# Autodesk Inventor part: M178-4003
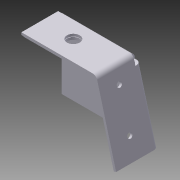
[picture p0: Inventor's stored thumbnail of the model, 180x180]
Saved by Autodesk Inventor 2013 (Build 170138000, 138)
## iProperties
Created: 2008-02
Part Number: M178-4003
Material: Aluminium - 6061
Document SubType Name: Sheet Metal
Designer: Autodesk, Inc.
Mass: 22.5137 g
Surface Area: 116.065 cm^2
Volume: 8.30765 cm^3
Density: 2.71 g/cm^3
Flat Pattern Width: 8.18641 cm
Flat Pattern Length: 9.33965 cm
Flat Pattern Area: 76.4582 cm^2
Sheet Metal Rule: Default
Sheet Metal Width: 3.223 in
Sheet Metal Length: 3.677 in
Sheet Metal Area: 11.851 in^2
Author: Autodesk, Inc.
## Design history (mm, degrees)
node "Face1"
node "Flange1"
cut "Cut1" dims "d16" = 1.524 (= Thickness), "d17" = 0
node "Flange2"
node "Flange3"
sketch "Sketch6"
  geometry: L1 (0, 0)-(23.876, 0) reference; L2 (23.876, 0)-(23.876, 45.72) reference; 3 further points
  constraints: 2 vertical alignment, 1 midpoint
  dimensions: "d45" = 25.4 distance of point (11.938, 12.7) point (11.938, 38.1); "d46" = 12.7 distance from line of L1 point (11.938, 12.7); "d47" = 11.938 distance from line of point (11.938, 0) L2 (derived)
hole "Hole1" sketch "Sketch6" diameter "d48" = 3.175; stored, may be unused: countersink angle "d52" = 82 deg, drill point angle "d54" = 118 deg; dims "d49" = 12.7, "d50" = 9.525, "d51" = 6.35, "d53" = 1.524 (= Thickness)
sketch "Sketch7"
  geometry: L1 (0, 0)-(0, 22.352) reference; 2 further points
  constraints: 1 horizontal alignment, 1 midpoint
  dimensions: "d55" = 20 distance from line of point (20, 11.176) L1
hole "Hole2" sketch "Sketch7" diameter "d56" = 8; stored, may be unused: countersink angle "d60" = 82 deg, drill point angle "d62" = 118 deg; dims "d57" = 12.7, "d58" = 9.525, "d59" = 6.35, "d61" = 1.524 (= Thickness)
body "Solid1"
sketch "Sketch1"
  geometry: L1 (0, 0)-(59.639, 0); L2 (59.639, 0)-(47.625, 44.628); L3 (47.625, 44.628)-(0, 44.628); L4 (0, 44.628)-(0, 0)
  constraints: 8 end point, 1 horizontal, 1 parallel, 1 vertical
  dimensions: "d0" = 44.6278 distance of L3.end L1.start; "d1" = 59.6392 distance of L1.start L1.end; "d2" = 47.625 distance of L2.end L3.end; "d34" = 105.067 deg angle of L2 L3 (derived)
face "Plate1" dims "Thickness" = 1.524
sketch "Sketch2"
  geometry: L1 through (-22.225, 0) direction (-1, 8.16e-34); L2 (-44.45, 0)-(-44.45, 25.4); L3 (-44.45, 25.4)-(0, 25.4); L4 through (0, 12.7) direction (0, -1)
  constraints: 6 end point, 1 horizontal, 1 perpendicular, 1 vertical
face "Plate2" dims "d4" = 1.524 (= BendReliefWidth), "d5" = 0.762 (= BendReliefDepth), "d6" = 3.048 (= MinimumRemnant), "d7" = 1.524 (= BendRadius), "d8" = 25.4, "d9" = 90 deg, "d10" = 1.524 (= BendRadius), "d11" = 6.096 (= CornerReliefSize), "d12" = 1.524 (= Thickness), "d13" = 1.524 (= JacobiRadiusSize), "d18" = 44.45, "d19" = 0, "SeamGap" = 0.00508, "Thickness" = 1.524
bend "Bend1" dims "d4" = 1.524 (= BendReliefWidth), "d5" = 0.762 (= BendReliefDepth), "d6" = 3.048 (= MinimumRemnant), "d7" = 1.524 (= BendRadius), "d8" = 25.4, "d9" = 90 deg, "d10" = 1.524 (= BendRadius), "SeamGap" = 0.00508, "Thickness" = 1.524
feature "Corner1" dims "d8" = 25.4, "d9" = 90 deg, "d11" = 6.096 (= CornerReliefSize), "d12" = 1.524 (= Thickness), "d13" = 1.524 (= JacobiRadiusSize)
sketch "Sketch3"
  geometry: L1 (0, -22.352)-(0, 0) reference; L2 (0, 0)-(44.45, 0) reference; L3 (44.45, -22.352)-(44.45, 0) reference; L4 (39.472, 0)-(44.45, -18.567)
  constraints: 2 end point, 2 point on line
  dimensions: "d20" = 4.9784 distance from line of L4.start L3; "d21" = 18.5674 distance from line of L4.end L2
sketch "Sketch4"
  geometry: L1 (-42.271, 0)-(3.449, 0); L2 (3.449, 0)-(3.449, 26.924); L3 (3.449, 26.924)-(-42.271, 26.924); L4 (-42.271, 26.924)-(-42.271, 0)
  constraints: 8 end point
face "Plate3" dims "d22" = 1.524 (= BendReliefWidth), "d23" = 0.762 (= BendReliefDepth), "d24" = 3.048 (= MinimumRemnant), "d25" = 1.524 (= BendRadius), "d26" = 25.4, "d27" = 90 deg, "d28" = 1.524 (= BendRadius), "d29" = 6.096 (= CornerReliefSize), "d30" = 1.524 (= Thickness), "d31" = 1.524 (= JacobiRadiusSize), "d32" = 45.72, "d33" = 0, "SeamGap" = 0.00508, "Thickness" = 1.524
bend "Bend2" dims "d22" = 1.524 (= BendReliefWidth), "d23" = 0.762 (= BendReliefDepth), "d24" = 3.048 (= MinimumRemnant), "d25" = 1.524 (= BendRadius), "d26" = 25.4, "d27" = 90 deg, "d28" = 1.524 (= BendRadius), "SeamGap" = 0.00508, "Thickness" = 1.524
feature "Corner2" dims "d26" = 25.4, "d27" = 90 deg, "d29" = 6.096 (= CornerReliefSize), "d30" = 1.524 (= Thickness), "d31" = 1.524 (= JacobiRadiusSize)
sketch "Sketch5"
  geometry: L1 through (0, 11.557) direction (-2.13e-32, -1); L2 through (22.403, 0) direction (1, 8.58e-34); L3 (44.806, 0)-(44.806, 23.114); L4 (44.806, 23.114)-(0, 23.114)
  constraints: 6 end point, 1 horizontal, 1 perpendicular, 1 vertical
face "Plate4" dims "d35" = 1.524 (= BendReliefWidth), "d36" = 0.762 (= BendReliefDepth), "d37" = 3.048 (= MinimumRemnant), "d38" = 1.524 (= BendRadius), "d39" = 47.1424, "d40" = 13.07822 (computed from d34), "d41" = 1.524 (= BendRadius), "d42" = 6.096 (= CornerReliefSize), "d43" = 1.524 (= Thickness), "d44" = 1.524 (= JacobiRadiusSize), "SeamGap" = 0.00508, "Thickness" = 1.524
bend "Bend3" dims "d35" = 1.524 (= BendReliefWidth), "d36" = 0.762 (= BendReliefDepth), "d37" = 3.048 (= MinimumRemnant), "d38" = 1.524 (= BendRadius), "d39" = 47.1424, "d40" = 13.07822 (computed from d34), "d41" = 1.524 (= BendRadius), "SeamGap" = 0.00508, "Thickness" = 1.524
feature "Corner3" dims "d39" = 47.1424, "d40" = 13.07822 (computed from d34), "d42" = 6.096 (= CornerReliefSize), "d43" = 1.524 (= Thickness), "d44" = 1.524 (= JacobiRadiusSize)
feature "Definition1"
other parameters: "BendRadius" = 1.524 (= Thickness), "BendReliefWidth" = 1.524 (= Thickness), "BendReliefDepth" = 0.762 (= 0.5 x Thickness), "CornerReliefSize" = 6.096 (= 4 x Thickness), "MinimumRemnant" = 3.048 (= 2 x Thickness), "TransitionRadius" = 1.524 (= BendRadius), "JacobiRadiusSize" = 1.524 (= BendRadius), "d3" = 1.524 (= BendRadius), "GapSize" = 1.524 (= Thickness), "BendRadius" = 1.524, "BendReliefDepth" = 0.762, "BendReliefWidth" = 1.524, "CornerReliefSize" = 6.096, "JacobiRadiusSize" = 1.524, "MinimumRemnant" = 3.048, "Thickness" = 1.524, "TransitionRadius" = 1.524, "GapSize" = 1.524
